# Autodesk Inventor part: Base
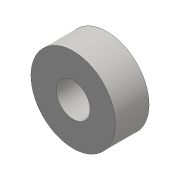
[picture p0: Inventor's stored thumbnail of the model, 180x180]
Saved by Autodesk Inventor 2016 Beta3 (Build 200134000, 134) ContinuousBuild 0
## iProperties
Created: 2016-03
Part Number: Base
Material: Generic
Document SubType Name: Modeling
Designer: Gaurav
Density: 1 g/cm^3
Appearance: Default
Author: Gaurav
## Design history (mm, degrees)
sketch "Sketch1"
  geometry: C1 r 12.5 at (0, 0); C2 r 5 at (0, 0); 1 further point
  constraints: 2 centre point, 2 coincident
  dimensions: "d0" = 25 diameter of C1; "d1" = 10 diameter of C2
extrude "Extrusion1" new body sketch "Sketch1" distance "d2" = 10; taper "d3" = 0 deg
body "Solid1"
